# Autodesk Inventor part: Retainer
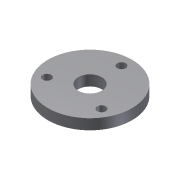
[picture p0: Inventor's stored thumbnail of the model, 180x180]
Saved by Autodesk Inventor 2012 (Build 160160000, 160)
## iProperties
Created: 2009-04
Part Number: Retainer
Document SubType Name: Modeling
Designer: Sham
Density: 1 g/cm^3
Material: Default
Author: Sham
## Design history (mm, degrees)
sketch "Sketch1"
  geometry: C1 r 100 at (0, 0); C2 r 28 at (0, 0)
  constraints: 2 centre point, 1 coincident
  dimensions: "d0" = 200 diameter of C1; "d1" = 56 diameter of C2
extrude "Extrusion2" new body sketch "Sketch1" distance "d10" = 25; taper "d11" = 0 deg
sketch "Sketch2"
  geometry: C1 r 28 at (0, 0) reference; 1 further point
  constraints: 1 vertical alignment
  dimensions: "d12" = 75 distance of C1.centre point (0, 75)
hole "Hole1" sketch "Sketch2" at (0, 75) diameter "d13" = 20.3; stored, may be unused: countersink angle "d17" = 90 deg, drill point angle "d19" = 118 deg; dims "d14" = 6, "d15" = 4, "d16" = 2, "d18" = 8
pattern_circular "Circular Pattern1" dims angle "d21" = 360 deg
body "Solid2"
